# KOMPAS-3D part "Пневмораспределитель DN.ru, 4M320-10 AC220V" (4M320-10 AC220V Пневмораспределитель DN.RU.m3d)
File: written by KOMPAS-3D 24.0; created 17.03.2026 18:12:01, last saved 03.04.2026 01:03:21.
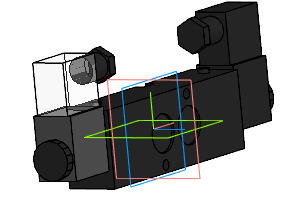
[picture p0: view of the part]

Document properties: Автор: R2D2; Полное имя файла: E:\Работа\Зайцев\Аксессуары для пневмоприводов\Пневмораспределители DN.ru\4M320 AC220V Пневмораспределитель DN.RU\4M320-10 AC220V Пневмораспределитель DN.RU\исходные материалы\4M320-10 AC220V Пневмораспределитель DN.RU.m3d

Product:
- Body: Тело 1  | qty 1
    Масса: 1.610491
- Body: Тело 3  | qty 1
    Масса: 1.610491
- Part/product: Пневмораспределитель DN.ru  | designation 4M320-10 AC220V
    Масса: 1.2
    Раздел спецификации: Прочие изделия
    Примечание: D290-00365

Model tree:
1. Эскиз:1
2. Элемент выдавливания:1
     Расстояние 1 = 118.8
3. Эскиз:2  (with: Грань.Элемент выдавливания:1)
4. Элемент выдавливания:2
     Расстояние 2 = 1.4
5. Эскиз:3  (with: Грань.Элемент выдавливания:1, Ребро.Элемент выдавливания:2)
6. Элемент выдавливания:3
     Расстояние 2 = 27
7. Эскиз:4  (with: Грань.Элемент выдавливания:1, Ребро.Элемент выдавливания:1)
8. Элемент выдавливания:4
     Расстояние 1 = 30
9. Эскиз:5  (with: Грань.Элемент выдавливания:4, Ребро.Элемент выдавливания:4)
10. Элемент выдавливания:5
     Расстояние 1 = 27
11. Эскиз:6  (with: Грань.Элемент выдавливания:4)
12. Элемент выдавливания:6
     Расстояние 1 = 5
13. Эскиз:7  (with: Грань.Элемент выдавливания:5)
14. Элемент выдавливания:7
     Расстояние 1 = 14
15. Эскиз:8  (with: Грань.Элемент выдавливания:7, Ребро.Элемент выдавливания:7)
16. Элемент выдавливания:8
     Расстояние 1 = 5
17. Эскиз:9  (with: Грань.Элемент выдавливания:1, Ребро.Элемент выдавливания:4)
18. Элемент выдавливания:9
     Расстояние 1 = 2.4
19. Эскиз:12  (with: Грань.Элемент выдавливания:9, Ребро.Элемент выдавливания:9)
20. Элемент выдавливания:12
     Расстояние 2 = 1
21. Эскиз:10  (with: Грань.Элемент выдавливания:1)
22. Элемент выдавливания:10
     Расстояние 2 = 5
23. пазы  (with: Грань.Элемент выдавливания:1, Ребро.Элемент выдавливания:3)
24. Элемент выдавливания:11
     Расстояние 2 = 5
25. Зеркальный массив:2
26. Экземпляр ( 1 )
27. Экземпляр ( 2 )  (with: Элемент выдавливания:4, Элемент выдавливания:6, Элемент выдавливания:5, Элемент выдавливания:7, Элемент выдавливания:8, Элемент выдавливания:9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)

Expressions: 4M320-10 AC220V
